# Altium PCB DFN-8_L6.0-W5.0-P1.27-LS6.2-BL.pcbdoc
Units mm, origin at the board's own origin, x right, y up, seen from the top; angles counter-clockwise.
Board outline 17.96 x 19.48 mm, 2 copper layers (Top Layer, Bottom Layer), stack 0 mm thick; 1 components, 0 nets, 9 pads, 0 vias.
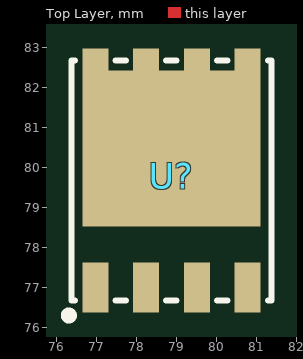
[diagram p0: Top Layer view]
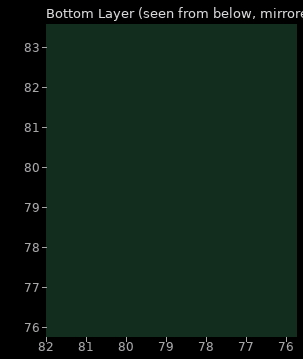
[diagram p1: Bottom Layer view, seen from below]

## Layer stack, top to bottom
Top Layer: signal copper (thickness not stored)
Bottom Layer: signal copper (thickness not stored)

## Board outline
87.815,69.85 69.85,69.85 69.85,89.33 87.815,89.33

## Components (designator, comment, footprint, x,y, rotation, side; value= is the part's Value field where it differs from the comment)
U? "" DFN-8_L6.0-W5.0-P1.27-LS6.2-BL 78.865,79.79 r0 top

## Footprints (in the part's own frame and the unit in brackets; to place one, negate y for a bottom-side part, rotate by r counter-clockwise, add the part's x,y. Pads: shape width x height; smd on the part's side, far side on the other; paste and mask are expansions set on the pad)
DFN-8_L6.0-W5.0-P1.27-LS6.2-BL [mm]
  rect 0.65x1.25 smd paste-100 mask+0.05: 1(-1.905,-2.79) 2(-0.635,-2.79) 3(0.635,-2.79) 4(1.905,-2.79)
  rect 0.65x0.8 smd paste-100 mask+0.05: 5(1.905,2.79) 6(0.635,2.79) 7(-0.635,2.79) 8(-1.905,2.79)
  rect 4.46x3.9 smd paste-100 mask+0.05: 8(0,0.685)
  silkscreen extent -2.66,-3.59 2.5,2.89

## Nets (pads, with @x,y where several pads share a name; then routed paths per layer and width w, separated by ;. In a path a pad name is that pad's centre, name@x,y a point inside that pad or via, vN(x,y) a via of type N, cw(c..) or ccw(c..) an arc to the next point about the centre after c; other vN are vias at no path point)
pads on no net: U?.1 U?.2 U?.3 U?.4 U?.5 U?.6 U?.7 U?.8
